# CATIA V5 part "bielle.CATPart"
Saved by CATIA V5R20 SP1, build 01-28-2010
Part number: bielle1
Bounding box of the stored display mesh (mm): x 55.993 to 87, y -10 to 5, z 28.093 to 41.907
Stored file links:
  E:\EDELI\gcausse\Edeli_2012_679_gcausse\bielle.CATPart
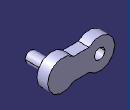
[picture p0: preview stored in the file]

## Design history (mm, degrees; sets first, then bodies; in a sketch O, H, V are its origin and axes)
Parameters
  long = 0.0170068
  diamtrou = 0.005
Body1 (main body)
  Sketch1 on zx-plane, origin (0, 0, 0), H (-1, 0, 0), V (0, 0, 1)
    line L1 (-67.8922, 40) -> (-75.101, 40)
    line L2 (-67.8922, 30) -> (-75.101, 30)
    arc A1 centre (-62.9932, 35) radius 7 from (-67.8922, 40) to (-67.8922, 30) cw
    point P5 (-62.9932, 35)
    point P6 (-58.0942, 30)
    arc A2 centre (-80, 35) radius 7 from (-75.101, 40) to (-75.101, 30) ccw
    point P7 (-80, 35)
    circle A3 centre (-62.9932, 35) radius 2.5
    distance P7 L1 = 5
    distance P5 L2 = 5
    distance L2 L1 = 10
    radius A1 = 7
    radius A2 = 7
    distance P5 P7 = 17.0068 {= long}
    radius A3 = 2.5
    horizontal: L1 H, L2 H
    coincidence: A1 P6, P6 L2
  Pad1: profile Sketch1, direction (0, 1, 0), length 5
  Sketch2 on start face of Pad1, origin (0, 0, 0), H (1, 0, 0), V (0, 0, 1)
    circle A1 centre (80, 35) radius 2.5
    reference projected arc E1 centre (80, 35) radius 7 from (75.101, 30) to (75.101, 40) ccw from edge [start face of Pad1 | face of Pad1 from Sketch1.A2]
    reference projected arc E2 centre (80, 35) radius 7 from (75.101, 30) to (75.101, 40) ccw from edge [start face of Pad1 | face of Pad1 from Sketch1.A2]
    radius A1 = 2.5
    radius E2 = 7 (reference)
    concentricity: A1 E1
  Pad2: profile Sketch2, direction (0, -1, 0), length 10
